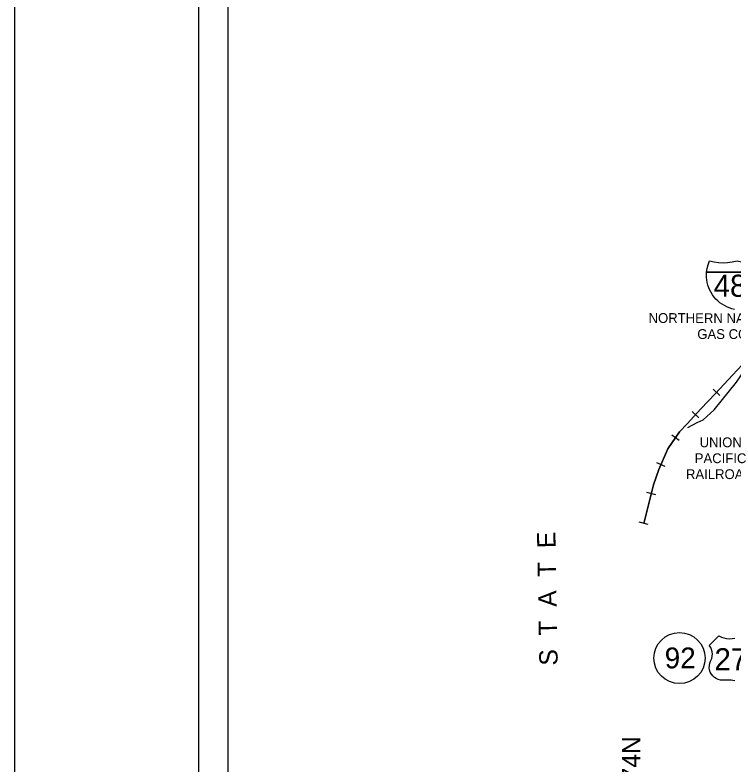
# Model space of a CAD drawing. Extents: x -132.8 to -73.3, y -60 to -26.
# Drawn here: x -132.82 to -126.96, y -53.27 to -47.16 of the extents above; entities that cross this region are included whole.
import ezdxf

# ---------------------------------------------------------------- set-up
doc = ezdxf.new("R2010")
doc.units = 0
for name, color, linetype in [('tdCoFrame', 7, 'Continuous'), ('tdCoPipeTxt', 7, 'Continuous'), ('tdCoPlotFrame', 7, 'Continuous'), ('tdCoRRCL', 7, 'Continuous'), ('tdCoRROwnerTxt', 7, 'Continuous'), ('tdCoShieldInt', 7, 'Continuous'), ('tdCoShieldStRte', 7, 'Continuous'), ('tdCoShieldUsRte', 7, 'Continuous'), ('tdCoStBndryTxt', 7, 'Continuous'), ('tdCoTwpRngTxt', 7, 'Continuous')]:
    doc.layers.add(name, color=color, linetype=linetype)

msp = doc.modelspace()

# ---------------------------------------------------------------- linework, layer by layer
at = {"layer": 'tdCoFrame'}
for points in [[(-131.3199, -27.0113), (-77.8199, -27.0113), (-77.8199, -59.0113), (-131.3199, -59.0113)], [(-131.0799, -27.2513), (-78.0599, -27.2513), (-78.0599, -58.7713), (-131.0799, -58.7713)]]:
    msp.add_lwpolyline(points, close=True, dxfattribs=at)
at = {"layer": 'tdCoPlotFrame'}
msp.add_lwpolyline([(-132.8199, -26.0113), (-76.8199, -26.0113), (-76.8199, -60.0113), (-132.8199, -60.0113)], close=True, dxfattribs=at)
at = {"layer": 'tdCoRRCL'}
for p, q in [((-127.0685, -50.2644), (-127.1233, -50.2132)), ((-127.2386, -50.447), (-127.294, -50.3964)), ((-127.3991, -50.6311), (-127.461, -50.5887)), ((-127.5135, -50.8442), (-127.5822, -50.8142)), ((-127.5914, -51.0748), (-127.6641, -51.0565)), ((-127.6522, -51.3172), (-127.725, -51.299))]:
    msp.add_line(p, q, dxfattribs=at)
for points in [[(-126.8415, -49.9672), (-126.9639, -50.0978), (-127.1037, -50.2471), (-127.2224, -50.3737), (-127.3342, -50.496), (-127.3966, -50.5611), (-127.4914, -50.6993), (-127.5646, -50.8677), (-127.6096, -50.9934), (-127.6886, -51.3081)], [(-127.6886, -51.3081), (-127.6096, -50.9934), (-127.5646, -50.8677), (-127.4914, -50.6993), (-127.3966, -50.5611), (-127.3342, -50.496), (-127.2224, -50.3737), (-127.1037, -50.2471), (-126.9639, -50.0978), (-126.8415, -49.9672)], [(-127.328, -50.5258), (-127.2529, -50.486), (-127.205, -50.4635), (-127.1144, -50.3807), (-126.9318, -50.1568), (-126.8957, -50.1041), (-126.8873, -50.0838)]]:
    msp.add_lwpolyline(points, dxfattribs=at)
at = {"layer": 'tdCoShieldInt'}
msp.add_line((-127.1754, -49.2582), (-126.6788, -49.2582), dxfattribs=at)
for points in [[(-126.9489, -49.5615), (-126.9703, -49.5564), (-126.9912, -49.5496), (-127.0115, -49.5413), (-127.0312, -49.5314), (-127.05, -49.52), (-127.0678, -49.5072), (-127.0846, -49.493), (-127.1003, -49.4776), (-127.1147, -49.461), (-127.1278, -49.4433), (-127.1395, -49.4247), (-127.1497, -49.4052), (-127.1584, -49.385), (-127.1655, -49.3642), (-127.1709, -49.3429), (-127.1747, -49.3212), (-127.1767, -49.2993), (-127.1771, -49.2774), (-127.176, -49.2582), (-127.1716, -49.2275), (-127.1638, -49.1974), (-127.1511, -49.1649), (-127.1152, -49.1736), (-127.0787, -49.1789), (-127.0418, -49.1809), (-127.0049, -49.1794), (-126.9683, -49.1746), (-126.9272, -49.1649)], [(-126.9489, -49.5615), (-126.9703, -49.5564), (-126.9912, -49.5496), (-127.0115, -49.5413), (-127.0312, -49.5314), (-127.05, -49.52), (-127.0678, -49.5072), (-127.0846, -49.493), (-127.1003, -49.4776), (-127.1147, -49.461), (-127.1278, -49.4433), (-127.1395, -49.4247), (-127.1497, -49.4052), (-127.1584, -49.385), (-127.1655, -49.3642), (-127.1709, -49.3429), (-127.1747, -49.3212), (-127.1767, -49.2993), (-127.1771, -49.2774), (-127.176, -49.2582), (-126.6783, -49.2582)]]:
    msp.add_lwpolyline(points, dxfattribs=at)
msp.add_lwpolyline([(-126.6783, -49.2582), (-127.176, -49.2582), (-127.1716, -49.2275), (-127.1638, -49.1974), (-127.1511, -49.1649), (-127.1152, -49.1736), (-127.0787, -49.1789), (-127.0418, -49.1809), (-127.0049, -49.1794), (-126.9683, -49.1746), (-126.9272, -49.1649), (-126.8913, -49.1736), (-126.8547, -49.1789), (-126.8178, -49.1809), (-126.7809, -49.1794), (-126.7443, -49.1746), (-126.7083, -49.1664), (-126.7032, -49.1649), (-126.6918, -49.1938), (-126.6835, -49.2238)], close=True, dxfattribs=at)
at = {"layer": 'tdCoShieldStRte'}
msp.add_circle((-127.3971, -52.4072), 0.2085, dxfattribs=at)
at = {"layer": 'tdCoShieldUsRte'}
msp.add_lwpolyline([(-126.9449, -52.5941), (-126.9613, -52.5899), (-126.9759, -52.5887), (-127.0445, -52.5887), (-127.0628, -52.5872), (-127.0806, -52.5826), (-127.0974, -52.5751), (-127.1127, -52.5649), (-127.1261, -52.5523), (-127.1372, -52.5376), (-127.1457, -52.5213), (-127.1513, -52.5038), (-127.154, -52.4856), (-127.1535, -52.4672), (-127.15, -52.4491), (-127.1436, -52.4319), (-127.1411, -52.4271), (-127.1338, -52.4103), (-127.1294, -52.3924), (-127.1281, -52.374), (-127.1299, -52.3557), (-127.1346, -52.3379), (-127.1423, -52.3212), (-127.1527, -52.306), (-127.1543, -52.3041), (-127.0754, -52.2253), (-127.0555, -52.2357), (-127.0344, -52.2433), (-127.0125, -52.248), (-126.9901, -52.2496), (-126.9677, -52.2481), (-126.9457, -52.2436)], dxfattribs=at)

# ---------------------------------------------------------------- texts
at = {"layer": 'tdCoPipeTxt'}
for s, p in [('NORTHERN NATURAL', (-127.6495, -49.6721)), ('GAS CO.', (-127.252, -49.8031))]:
    msp.add_text(s, height=0.08, rotation=359.90479, dxfattribs=at).set_placement(p)
at = {"layer": 'tdCoRROwnerTxt'}
for s, p in [('UNION', (-127.233, -50.6866)), ('PACIFIC', (-127.2731, -50.8166)), ('RAILROAD', (-127.3445, -50.9466))]:
    msp.add_text(s, height=0.08, dxfattribs=at).set_placement(p)
at = {"layer": 'tdCoShieldInt'}
msp.add_text('480', height=0.18, dxfattribs=at).set_placement((-127.1187, -49.459))
at = {"layer": 'tdCoShieldStRte'}
msp.add_text('92', height=0.17, dxfattribs=at).set_placement((-127.5178, -52.4911))
at = {"layer": 'tdCoShieldUsRte'}
msp.add_text('275', height=0.18, dxfattribs=at).set_placement((-127.1117, -52.5066))
at = {"layer": 'tdCoStBndryTxt'}
msp.add_text('S  T  A  T  E', height=0.15, rotation=91.03458, dxfattribs=at).set_placement((-128.3905, -52.4673))
at = {"layer": 'tdCoTwpRngTxt'}
msp.add_text('T-74N', height=0.15, rotation=89.90553, dxfattribs=at).set_placement((-127.7163, -53.603))

doc.saveas('drawing.dxf')
